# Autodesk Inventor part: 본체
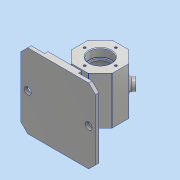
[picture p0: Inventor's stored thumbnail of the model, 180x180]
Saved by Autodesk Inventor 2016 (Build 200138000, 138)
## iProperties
Created: 2018-06
Part Number: 본체
Material: 알루미늄 6061
Document SubType Name: Modeling
Designer: 605-07
Density: 2.7 g/cm^3
Appearance: 알루미늄 - 평지
Mass: 551.774 g
Surface Area: 602.625 cm^2
Volume: 204.361 cm^3
Author: 605-07
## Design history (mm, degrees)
sketch "스케치1"
  geometry: L1 (12.426, 30)-(30, 12.426); L2 (30, 12.426)-(30, -12.426); L3 (30, -12.426)-(12.426, -30); L4 (12.426, -30)-(-12.426, -30); L5 (-12.426, -30)-(-30, -12.426); L6 (-30, -12.426)-(-30, 12.426); L7 (-30, 12.426)-(-12.426, 30); L8 (-12.426, 30)-(12.426, 30); 3 further points
  constraints: 16 end point, 1 coincident, 1 midpoint, 1 vertical alignment, 17 other
  dimensions: "d1" = 30 distance from line of point (0, 0) L8
extrude "돌출1" new body sketch "스케치1" distance "d2" = 70; taper "d3" = 0 deg
sketch "스케치2"
  geometry: C1 r 16 at (0, 0); 1 further point
  constraints: 1 centre point, 1 coincident
  dimensions: "d4" = 32 diameter of C1
extrude "돌출2" cut sketch "스케치2" distance "d5" = 12; taper "d6" = 0 deg
sketch "스케치3"
  geometry: C1 r 14 at (0, 0); 1 further point
  constraints: 1 centre point, 1 coincident
  dimensions: "d7" = 28 diameter of C1
extrude "돌출3" cut sketch "스케치3" distance "d8" = 3; taper "d9" = 0 deg
sketch "스케치4"
  geometry: C1 r 25 at (0, 0); 1 further point
  constraints: 1 centre point, 1 coincident
  dimensions: "d10" = 50 diameter of C1
extrude "돌출4" cut sketch "스케치4" distance "d11" = 40; taper "d12" = 0 deg
node "작업 평면1"
chamfer "모따기1" distance "d13" = 1; stored, may be unused: second distance "d14" = 2, angle "d15" = 45 deg
fillet "모깎기1" dims "d16" = 0.3
fillet "모깎기2" dims "d17" = 3
sketch "스케치5" dims "d18" = 46
  geometry: L1 (0, 0)-(0, 23); 2 further points
  constraints: 2 coincident, 2 end point, 1 vertical, 1 vertical alignment, 2 other
hole "구멍1" sketch "스케치5" at (0, 23) diameter "d19" = 3.459; stored, may be unused: countersink angle "d23" = 90 deg, drill point angle "d25" = 118 deg; dims "d20" = 8, "d21" = 4, "d22" = 2, "d24" = 10
node "작업 평면2"
node "작업 평면3"
sketch "스케치6"
  geometry: L1 (55, 90)-(-55, 90); L2 (-55, 90)-(-55, -20); L3 (-55, -20)-(55, -20); L4 (55, -20)-(55, 90); L5 (12.426, 0)-(-12.426, 0) reference; L6 (30, 0)-(30, 70) reference; 5 further points
  constraints: 8 end point, 4 midpoint, 2 parallel, 1 horizontal, 1 horizontal alignment, 1 perpendicular, 1 vertical alignment
  dimensions: "d30" = 55 distance from line of L4 point (0, -20); "d31" = 110 distance between parallel lines of L1 L3
extrude "돌출5" join sketch "스케치6" distance "d32" = 5; taper "d33" = 0 deg
chamfer "모따기2" distance "d34" = 10; stored, may be unused: second distance "d35" = 2, angle "d36" = 45 deg
sketch "스케치7"
  geometry: L1 (-25, -90)-(25, -90); L2 (25, -90)-(25, 20); L3 (25, 20)-(-25, 20); L4 (-25, 20)-(-25, -90); L5 (45, 20)-(-45, 20) reference; L6 (-45, -90)-(45, -90) reference; L7 (-55, 10)-(-55, -80) reference; L8 (55, -80)-(55, 10) reference; 1 further point
  constraints: 8 end point, 2 parallel, 2 point on line, 1 horizontal, 1 perpendicular
  dimensions: "d37" = 30 distance between parallel lines of L7 L4; "d38" = 30 distance between parallel lines of L8 L2
extrude "돌출6" join sketch "스케치7" distance "d39" = 5; taper "d40" = 0 deg
sketch "스케치8"
  geometry: L1 (55, -80)-(55, 10) reference; L2 (30, 0)-(30, -70) reference; C1 r 5 at (45, -35); 2 further points
  constraints: 1 centre point, 1 horizontal alignment, 1 midpoint
  dimensions: "d41" = 10 diameter of C1; "d42" = 10 distance from line of L1 C1.centre
extrude "돌출7" cut sketch "스케치8" distance "d43" = 5; taper "d44" = 0 deg
sketch "스케치9"
  geometry: L1 (0, -54)-(0, -16); L2 (5, -54)-(5, -16); L3 (-5, -16)-(-5, -54); L4 (-25, -90)-(-25, 20) reference; C1 r 5 at (-45, -35) reference; A1 r 5 centre (0, -54) between (-5, -54) and (5, -54); A2 r 5 centre (0, -16) between (5, -16) and (-5, -16); 2 further points
  constraints: 8 end point, 4 point on circle, 4 tangent, 2 centre point, 1 horizontal alignment, 1 midpoint, 1 parallel, 1 vertical, 1 vertical alignment
  dimensions: "d45" = 38 distance of L1.end L1.start; "d46" = 10 distance between parallel lines of L3 L2
extrude "돌출8" join sketch "스케치9" stored distance "d47" = 5; taper "d48" = 0 deg
fillet "모깎기3" dims "d49" = 2
sketch "스케치10"
  geometry: L1 (0, 0)-(-21.213, 21.213); L2 (0, 0)-(0, 30); L3 (12.426, 30)-(-12.426, 30) reference; L4 (-12.426, 30)-(-30, 12.426) reference
  constraints: 4 end point, 2 midpoint, 1 vertical
  dimensions: "d50" = 45 deg angle of L2 L1
sketch "스케치11"
  geometry: L1 (-24.853, 70)-(0, 70) reference; L2 (0, 0)-(-24.853, 0) reference; C1 r 8 at (-12.426, 35); 5 further points
  constraints: 1 centre point, 1 midpoint, 1 vertical alignment
  dimensions: "d52" = 16 diameter of C1; "d53" = 35 distance from line of L1 C1.centre
extrude "돌출9" join sketch "스케치11" distance "d54" = 7; taper "d55" = 0 deg
fillet "모깎기4" dims "d56" = 3
sketch "스케치13"
  geometry: C1 r 4 at (0, 0); 5 further points
  constraints: 1 centre point, 1 coincident
  dimensions: "d58" = 8 diameter of C1
extrude "돌출10" cut sketch "스케치13" stored distance "d59" = 7; taper "d60" = 0 deg
fillet "모깎기5" dims "d61" = 1
sketch "스케치14"
  geometry: L1 (24.024, -70)-(0, -70) reference; L2 (-17.988, 0)-(-17.988, -70) reference; 2 further points
  constraints: 1 other
  dimensions: "d62" = 35 distance from line of L1 point (12.012, -35); "d63" = 30 distance from line of L2 point (12.012, -35)
feature "엠보싱1" sketch "스케치14" dims "d64" = 0.5, "d65" = 0
chamfer "모따기3" distance "d66" = 1; stored, may be unused: second distance "d67" = 2, angle "d68" = 45 deg
node "솔리드1"
mirror "대칭1"
pattern_circular "원형 패턴1" dims angle "d27" = 360 deg
mirror "대칭2"
mirror "대칭3"
other parameters: "d29" = -62
